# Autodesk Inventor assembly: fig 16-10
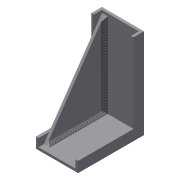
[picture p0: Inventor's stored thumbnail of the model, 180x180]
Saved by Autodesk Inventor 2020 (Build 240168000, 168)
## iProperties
Created: 2003-01
Part Number: fig 16-10
Document SubType Name: Weldment
Designer: Owner
Control State: 0
Master: False
Checked Out: False
Shininess: 64.0
Length Units: 11269
Angle Units: 11279
Time Units: 11290
Mass Units: 11283
Length Display Precision: 3
Angle Display Precision: 2
Compacted: True
Density: 0.0
Volumn: 0.0
Area: 0.0
PropertySet Name: Model Information
Author: Owner
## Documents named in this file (3)
- D:\Autodesk Inventor_2020\Resources\Resources\Inventor_2020_Part\Inventor_2020_Part\c16_Inv_2020_prt\fig 16-10\fig 16-10.iam
- D:\Autodesk Inventor_2020\Resources\Resources\Inventor_2020_Part\Inventor_2020_Part\c16_Inv_2020_prt\fig 16-10\Bracket-1.ipt
- D:\Autodesk Inventor_2020\Resources\Resources\Inventor_2020_Part\Inventor_2020_Part\c16_Inv_2020_prt\fig 16-10\Bracket-plate.ipt
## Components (2 placed, 2 different names)
1. Bracket-1:1 — Mate:1, Mate:2
2. Bracket-plate:1 — Mate:1, Mate:2
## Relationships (2: Mate 2)
- Mate:1: Bracket-1:1 ↔ Bracket-plate:1
- Mate:2: Bracket-1:1 ↔ Bracket-plate:1
